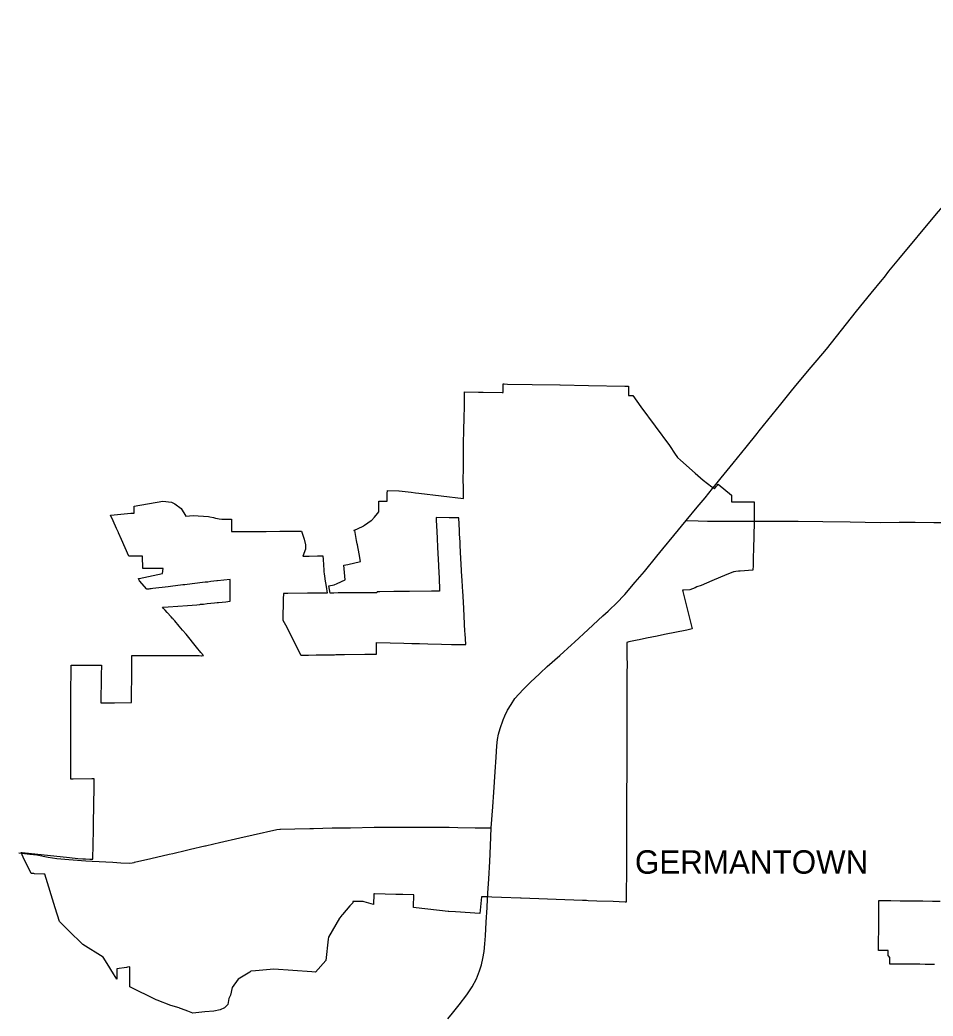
# Model space of a CAD drawing. Extents: x 0 to 34, y 0 to 22.
# Drawn here: x 4.3764 to 4.6894, y 14.3323 to 14.6736 of the extents above; entities that cross this region are included whole.
import ezdxf

# ---------------------------------------------------------------- set-up
doc = ezdxf.new("R2010")
doc.units = 0
for name, color, linetype in [('GM_X_Corporation', 7, 'Continuous'), ('GM_X_Corporation_Text', 7, 'Continuous'), ('GM_X_State_Route', 7, 'Continuous')]:
    doc.layers.add(name, color=color, linetype=linetype)

msp = doc.modelspace()

# ---------------------------------------------------------------- linework, layer by layer
at = {"layer": 'GM_X_Corporation'}
msp.add_lwpolyline([(4.41464, 14.4397), (4.41468, 14.44341), (4.41469, 14.44458), (4.41471, 14.44643), (4.41472, 14.44729), (4.41481, 14.45559), (4.41481, 14.45583), (4.4151, 14.45583), (4.41698, 14.45583), (4.42499, 14.4558), (4.43542, 14.45577), (4.43779, 14.45577), (4.43869, 14.45576), (4.4387, 14.45576), (4.43929, 14.45578), (4.43844, 14.45684), (4.43694, 14.4587), (4.43338, 14.46313), (4.43215, 14.46456), (4.43104, 14.46586), (4.42945, 14.46772), (4.42897, 14.46827), (4.4289, 14.46836), (4.42863, 14.46865), (4.42825, 14.46908), (4.42691, 14.47057), (4.42616, 14.4714), (4.42555, 14.47208), (4.42532, 14.47235), (4.42554, 14.47236), (4.42717, 14.47249), (4.43384, 14.47299), (4.43704, 14.47323), (4.43804, 14.47331), (4.43804, 14.47333), (4.43831, 14.47336), (4.43932, 14.47346), (4.4406, 14.47359), (4.44188, 14.47372), (4.44315, 14.47385), (4.444, 14.47394), (4.44443, 14.47398), (4.44571, 14.47411), (4.44699, 14.47424), (4.44771, 14.47431), (4.44843, 14.47439), (4.44844, 14.47439), (4.44844, 14.4746), (4.44845, 14.47555), (4.44845, 14.47629), (4.44845, 14.4764), (4.44846, 14.47799), (4.44847, 14.47951), (4.44847, 14.47969), (4.44848, 14.48139), (4.44848, 14.4819), (4.44409, 14.48138), (4.44394, 14.48137), (4.44189, 14.48113), (4.44081, 14.481), (4.44024, 14.48093), (4.43994, 14.4809), (4.43543, 14.48037), (4.43291, 14.48007), (4.43268, 14.48005), (4.43221, 14.47999), (4.42804, 14.4795), (4.42716, 14.4794), (4.42196, 14.47878), (4.42139, 14.47871), (4.42091, 14.47865), (4.42059, 14.47861), (4.41994, 14.47854), (4.41744, 14.48144), (4.4171, 14.4822), (4.41726, 14.48223), (4.42523, 14.4839), (4.4255, 14.48559), (4.41853, 14.48559), (4.41843, 14.48988), (4.41534, 14.48987), (4.41372, 14.48986), (4.41122, 14.49553), (4.41021, 14.49781), (4.41014, 14.49799), (4.41019, 14.49799), (4.40955, 14.49937), (4.40836, 14.50193), (4.40744, 14.50391), (4.40873, 14.50402), (4.41441, 14.50455), (4.41552, 14.50465), (4.41553, 14.50619), (4.41554, 14.50702), (4.42541, 14.50866), (4.42835, 14.50833), (4.42955, 14.5078), (4.43165, 14.50617), (4.43332, 14.50362), (4.43575, 14.50382), (4.44105, 14.5034), (4.44148, 14.50337), (4.44279, 14.50306), (4.44344, 14.50291), (4.44414, 14.50279), (4.44474, 14.5027), (4.44556, 14.50256), (4.44743, 14.50252), (4.44888, 14.50257), (4.44888, 14.50247), (4.44888, 14.50147), (4.44887, 14.49828), (4.45096, 14.4983), (4.45252, 14.49831), (4.45646, 14.49834), (4.45752, 14.49835), (4.4602, 14.49837), (4.46082, 14.49837), (4.46553, 14.49841), (4.46615, 14.49842), (4.46631, 14.49842), (4.46662, 14.49842), (4.46718, 14.49843), (4.46778, 14.49843), (4.46815, 14.49843), (4.46829, 14.49843), (4.47072, 14.49845), (4.47111, 14.49846), (4.47128, 14.49846), (4.47167, 14.49846), (4.472, 14.49846), (4.47267, 14.49847), (4.47288, 14.49847), (4.47289, 14.49845), (4.47335, 14.49709), (4.47379, 14.49573), (4.47431, 14.49376), (4.47426, 14.49222), (4.47339, 14.48985), (4.47552, 14.48989), (4.47838, 14.48995), (4.47943, 14.48997), (4.4802, 14.48998), (4.48029, 14.48874), (4.48056, 14.48505), (4.4806, 14.48455), (4.48069, 14.48377), (4.48079, 14.483), (4.4809, 14.48223), (4.48095, 14.48194), (4.48135, 14.47945), (4.48171, 14.47724), (4.48171, 14.47722), (4.48128, 14.47722), (4.48034, 14.47721), (4.48005, 14.47721), (4.47495, 14.47717), (4.46823, 14.47712), (4.46819, 14.47712), (4.46771, 14.47712), (4.46742, 14.47712), (4.46672, 14.47711), (4.46669, 14.47711), (4.46664, 14.47518), (4.46662, 14.47407), (4.46661, 14.47375), (4.46658, 14.47269), (4.46653, 14.47028), (4.46651, 14.46941), (4.4665, 14.46889), (4.46648, 14.46803), (4.46654, 14.46791), (4.46738, 14.46629), (4.47255, 14.45618), (4.47266, 14.45595), (4.4729, 14.45595), (4.47385, 14.45597), (4.47394, 14.45597), (4.47407, 14.45597), (4.47529, 14.45599), (4.47791, 14.45602), (4.47845, 14.45603), (4.47891, 14.45604), (4.48, 14.45605), (4.48068, 14.45606), (4.48418, 14.45611), (4.48467, 14.45612), (4.48514, 14.45613), (4.48678, 14.45615), (4.48762, 14.45616), (4.49468, 14.45626), (4.49784, 14.45631), (4.49861, 14.45632), (4.49862, 14.45747), (4.49864, 14.4595), (4.49864, 14.45956), (4.49864, 14.46032), (4.50803, 14.46006), (4.51068, 14.45999), (4.51333, 14.45992), (4.51626, 14.45984), (4.52091, 14.45971), (4.52434, 14.45965), (4.52816, 14.45957), (4.52897, 14.45956), (4.5292, 14.45956), (4.52896, 14.46338), (4.52892, 14.46405), (4.52852, 14.47193), (4.52828, 14.47619), (4.52819, 14.47787), (4.52811, 14.47921), (4.52797, 14.48172), (4.52791, 14.4828), (4.52768, 14.48709), (4.52757, 14.4891), (4.52732, 14.49352), (4.52725, 14.49472), (4.5271, 14.4974), (4.52703, 14.49865), (4.52679, 14.50297), (4.52353, 14.50303), (4.51907, 14.50311), (4.51911, 14.50222), (4.5193, 14.4983), (4.51941, 14.49593), (4.51955, 14.493), (4.51985, 14.48667), (4.51998, 14.484), (4.52005, 14.48258), (4.52026, 14.47807), (4.52027, 14.47787), (4.51749, 14.47785), (4.50994, 14.47778), (4.50927, 14.47777), (4.50461, 14.47773), (4.49981, 14.47769), (4.4988, 14.47768), (4.49879, 14.47735), (4.49747, 14.47734), (4.49342, 14.47731), (4.4915, 14.4773), (4.49079, 14.47729), (4.48985, 14.47729), (4.48851, 14.47728), (4.48778, 14.47727), (4.48622, 14.47726), (4.48543, 14.47725), (4.48398, 14.47724), (4.48269, 14.47723), (4.48228, 14.47974), (4.48406, 14.47999), (4.48512, 14.48048), (4.48785, 14.48177), (4.48738, 14.48675), (4.48876, 14.48704), (4.49317, 14.48799), (4.49268, 14.49061), (4.4921, 14.49371), (4.49202, 14.49412), (4.49182, 14.4952), (4.49123, 14.49861), (4.49084, 14.49861), (4.49087, 14.49863), (4.49402, 14.50015), (4.49422, 14.50029), (4.49451, 14.50049), (4.49674, 14.50204), (4.49687, 14.50213), (4.4979, 14.50319), (4.49897, 14.50452), (4.49898, 14.50454), (4.4994, 14.50507), (4.4994, 14.50559), (4.4994, 14.50776), (4.4994, 14.50789), (4.4994, 14.50868), (4.50146, 14.50869), (4.50227, 14.5087), (4.50232, 14.51133), (4.50234, 14.51237), (4.50623, 14.51227), (4.50634, 14.51225), (4.5084, 14.512), (4.51052, 14.51174), (4.51196, 14.51156), (4.51313, 14.51142), (4.52844, 14.50968), (4.52843, 14.5115), (4.52842, 14.51201), (4.52838, 14.51738), (4.5284, 14.51849), (4.5284, 14.51887), (4.52844, 14.52251), (4.52845, 14.52358), (4.52847, 14.52555), (4.52848, 14.52659), (4.52848, 14.52679), (4.5285, 14.52816), (4.5285, 14.52825), (4.52859, 14.53324), (4.52866, 14.53708), (4.52867, 14.53753), (4.52873, 14.54088), (4.52875, 14.54182), (4.52883, 14.54612), (4.5336, 14.54606), (4.53516, 14.54605), (4.54173, 14.54598), (4.54205, 14.54597), (4.54205, 14.54617), (4.54209, 14.54887), (4.54242, 14.54887), (4.54352, 14.54885), (4.55196, 14.5487), (4.5615, 14.54853), (4.56163, 14.54853), (4.57124, 14.54837), (4.58376, 14.54815), (4.58505, 14.54813), (4.58501, 14.54492), (4.58644, 14.54488), (4.58925, 14.54106), (4.599, 14.52776), (4.59924, 14.52741), (4.60078, 14.52517), (4.60185, 14.52363), (4.60282, 14.52278), (4.60789, 14.51831), (4.61056, 14.51596), (4.61361, 14.51365), (4.61399, 14.51336), (4.61401, 14.51334), (4.61448, 14.51294), (4.61449, 14.51294), (4.61519, 14.51382), (4.6155, 14.51419), (4.61573, 14.51449), (4.6203, 14.5108), (4.6203, 14.50851), (4.62289, 14.5085), (4.62549, 14.50848), (4.62809, 14.50847), (4.62808, 14.50422), (4.62807, 14.50262), (4.62806, 14.50197), (4.62804, 14.50149), (4.62782, 14.49228), (4.62775, 14.48949), (4.62768, 14.48665), (4.62764, 14.48512), (4.62327, 14.48472), (4.6227, 14.48467), (4.6218, 14.48459), (4.62123, 14.48454), (4.62101, 14.48452), (4.62073, 14.4844), (4.61875, 14.48358), (4.6136, 14.48143), (4.60985, 14.47987), (4.60847, 14.4793), (4.60788, 14.47905), (4.60602, 14.47828), (4.60401, 14.4782), (4.60366, 14.47818), (4.60353, 14.47818), (4.60684, 14.46494), (4.60502, 14.46456), (4.59731, 14.46298), (4.59482, 14.46246), (4.59122, 14.46172), (4.58866, 14.4612), (4.58798, 14.46106), (4.58509, 14.46046), (4.58477, 14.46039), (4.58438, 14.46031), (4.58438, 14.45944), (4.58439, 14.45905), (4.58439, 14.459), (4.58441, 14.45625), (4.58441, 14.45479), (4.58449, 14.45327), (4.58447, 14.44937), (4.58447, 14.44736), (4.58443, 14.43472), (4.58442, 14.43171), (4.58441, 14.42931), (4.58438, 14.41858), (4.58439, 14.41632), (4.58439, 14.41557), (4.58438, 14.4135), (4.58438, 14.41269), (4.58437, 14.41168), (4.58437, 14.41028), (4.58436, 14.40904), (4.58435, 14.40791), (4.58435, 14.40651), (4.58433, 14.40285), (4.58431, 14.39712), (4.58431, 14.39648), (4.5843, 14.39459), (4.5843, 14.39417), (4.58429, 14.39203), (4.58429, 14.39149), (4.58429, 14.39028), (4.58429, 14.38921), (4.58429, 14.38787), (4.58428, 14.38602), (4.58429, 14.38225), (4.58425, 14.37383), (4.58423, 14.37133), (4.58387, 14.37134), (4.5798, 14.37149), (4.57409, 14.3717), (4.5712, 14.37181), (4.57063, 14.37183), (4.56945, 14.37188), (4.56925, 14.37188), (4.5482, 14.37266), (4.54802, 14.37267), (4.54144, 14.37292), (4.53816, 14.37304), (4.53675, 14.37309), (4.53486, 14.37316), (4.5346, 14.37317), (4.53408, 14.36744), (4.53403, 14.36744), (4.52575, 14.36796), (4.52342, 14.36811), (4.52324, 14.36812), (4.51219, 14.36934), (4.51135, 14.36943), (4.51136, 14.3697), (4.51145, 14.37378), (4.50762, 14.37388), (4.50675, 14.37391), (4.50618, 14.37392), (4.50572, 14.37393), (4.50562, 14.37394), (4.50529, 14.37394), (4.49798, 14.37414), (4.49774, 14.37414), (4.4977, 14.37314), (4.49769, 14.37305), (4.49762, 14.37148), (4.49758, 14.37053), (4.49677, 14.37076), (4.49439, 14.37142), (4.49404, 14.37151), (4.49378, 14.37153), (4.49317, 14.37154), (4.49162, 14.37155), (4.4912, 14.37156), (4.49113, 14.37156), (4.49087, 14.37156), (4.49049, 14.37157), (4.49049, 14.37139), (4.49055, 14.37111), (4.4905, 14.37105), (4.48971, 14.37026), (4.48949, 14.37001), (4.487, 14.36708), (4.48678, 14.36682), (4.48648, 14.36647), (4.48598, 14.3658), (4.48218, 14.35927), (4.48211, 14.35866), (4.48128, 14.35137), (4.47776, 14.3473), (4.47646, 14.34739), (4.46341, 14.34831), (4.45713, 14.34775), (4.45565, 14.34762), (4.45556, 14.34761), (4.4552, 14.34737), (4.45126, 14.34488), (4.44917, 14.34208), (4.44863, 14.33945), (4.44805, 14.33834), (4.44766, 14.33624), (4.44647, 14.33513), (4.44509, 14.33441), (4.44291, 14.3339), (4.43976, 14.33368), (4.43567, 14.33323), (4.43395, 14.33393), (4.43173, 14.3348), (4.43114, 14.33503), (4.43102, 14.33507), (4.42812, 14.33588), (4.42342, 14.33772), (4.42308, 14.33786), (4.41412, 14.3423), (4.41413, 14.34829), (4.41413, 14.34909), (4.41328, 14.34898), (4.41297, 14.34894), (4.40966, 14.3485), (4.40966, 14.34531), (4.40966, 14.34488), (4.40846, 14.34679), (4.40626, 14.35027), (4.4049, 14.35244), (4.39799, 14.3568), (4.39308, 14.36165), (4.39184, 14.36287), (4.39, 14.36468), (4.38852, 14.36936), (4.38489, 14.38089), (4.38463, 14.3809), (4.38144, 14.38107), (4.3812, 14.38109), (4.38023, 14.38114), (4.37757, 14.38675), (4.37681, 14.38835), (4.37722, 14.38831), (4.39336, 14.38656), (4.39627, 14.38632), (4.39794, 14.38619), (4.39891, 14.38614), (4.40038, 14.38605), (4.40073, 14.38603), (4.40144, 14.38599), (4.40159, 14.39611), (4.40167, 14.40085), (4.40168, 14.40186), (4.40186, 14.41347), (4.40186, 14.41352), (4.40182, 14.41352), (4.40105, 14.41352), (4.40105, 14.41352), (4.39467, 14.41348), (4.3938, 14.41348), (4.3938, 14.41397), (4.39381, 14.4163), (4.39382, 14.42031), (4.39385, 14.42877), (4.39385, 14.43059), (4.39386, 14.43208), (4.39387, 14.43583), (4.39389, 14.44182), (4.39392, 14.45246), (4.3953, 14.45247), (4.40039, 14.45251), (4.40377, 14.45253), (4.40433, 14.45254), (4.40432, 14.45229), (4.40429, 14.44937), (4.40426, 14.44725), (4.40418, 14.44084), (4.40416, 14.4396), (4.40881, 14.43965)], close=True, dxfattribs=at)
msp.add_lwpolyline([(4.68985, 14.34997), (4.68674, 14.34999), (4.68484, 14.35001), (4.683, 14.35002), (4.68253, 14.35002), (4.68229, 14.35003), (4.68161, 14.35003), (4.68097, 14.35004), (4.67879, 14.35005), (4.67563, 14.35007), (4.67454, 14.35008), (4.67454, 14.35172), (4.67455, 14.35237), (4.67408, 14.35286), (4.67399, 14.35295), (4.67405, 14.3547), (4.67353, 14.3547), (4.67068, 14.35472), (4.67068, 14.3554), (4.6707, 14.3572), (4.67075, 14.3625), (4.67076, 14.36413), (4.67077, 14.36463), (4.6708, 14.36744), (4.67083, 14.36949), (4.67084, 14.37085), (4.67085, 14.37188), (4.67221, 14.37186), (4.67497, 14.37183), (4.67815, 14.37179), (4.68226, 14.37175), (4.68353, 14.37173), (4.68475, 14.37172), (4.68586, 14.37171), (4.6892, 14.37167), (4.69179, 14.37164)], dxfattribs=at)
at = {"layer": 'GM_X_State_Route'}
for p, q in [((4.57798, 14.471), (4.57858, 14.47157)), ((4.52311, 14.33132), (4.52468, 14.33327))]:
    msp.add_line(p, q, dxfattribs=at)
for points in [[(4.67425, 14.58751), (4.67767, 14.59166), (4.69056, 14.6072), (4.6927, 14.6097), (4.69743, 14.6154), (4.70004, 14.61862), (4.70413, 14.62384), (4.70902, 14.63035), (4.71286, 14.63549), (4.71914, 14.64394), (4.74073, 14.67225), (4.74179, 14.67361)], [(4.67195, 14.5846), (4.67269, 14.58552), (4.67425, 14.58751)], [(4.62976, 14.53276), (4.63719, 14.54196), (4.64091, 14.54652), (4.64298, 14.54902), (4.64761, 14.55459), (4.64963, 14.557), (4.65283, 14.56085), (4.66319, 14.57386), (4.66819, 14.58), (4.67195, 14.5846)], [(4.6149, 14.51442), (4.61671, 14.51665), (4.62084, 14.52169), (4.62531, 14.52723), (4.62907, 14.53191), (4.62976, 14.53276)], [(4.60473, 14.50206), (4.60858, 14.50669), (4.61125, 14.5099), (4.61384, 14.5131), (4.6149, 14.51442)], [(4.58377, 14.47678), (4.58731, 14.48092), (4.59044, 14.48465), (4.59472, 14.48981), (4.5968, 14.49234), (4.60053, 14.49689), (4.60473, 14.50206)], [(4.60473, 14.50206), (4.60887, 14.50195), (4.61213, 14.5019), (4.62094, 14.50181), (4.62553, 14.50183), (4.62749, 14.50188)], [(4.62749, 14.50188), (4.62876, 14.50191), (4.63087, 14.50186), (4.63625, 14.50186), (4.63938, 14.50186), (4.64318, 14.50182), (4.65163, 14.50174), (4.66099, 14.50165), (4.67127, 14.50145)], [(4.67127, 14.50145), (4.67778, 14.50149), (4.68322, 14.50148), (4.68968, 14.50141), (4.69377, 14.50136), (4.70177, 14.5013), (4.71183, 14.50119), (4.72194, 14.50107), (4.72894, 14.50099), (4.73136, 14.50096), (4.73821, 14.50091), (4.74295, 14.50089), (4.75114, 14.50079), (4.7577, 14.50079)], [(4.57858, 14.47157), (4.58078, 14.47366), (4.58372, 14.47671), (4.58377, 14.47678)], [(4.56548, 14.45949), (4.56649, 14.4604), (4.57121, 14.46469), (4.57624, 14.46941), (4.57798, 14.471)], [(4.55475, 14.44983), (4.55714, 14.45201), (4.56144, 14.45582), (4.56548, 14.45949)], [(4.54357, 14.43708), (4.54483, 14.43907), (4.54608, 14.44106), (4.54738, 14.44262), (4.549, 14.44432), (4.55149, 14.44682), (4.55437, 14.44948), (4.55475, 14.44983)], [(4.53794, 14.39681), (4.53854, 14.404), (4.53887, 14.40898), (4.53927, 14.41598), (4.5396, 14.42103), (4.53985, 14.42484), (4.54014, 14.42708), (4.54049, 14.42888), (4.54096, 14.43077), (4.54199, 14.43379), (4.5426, 14.4352), (4.54357, 14.43708)], [(4.41571, 14.38497), (4.42132, 14.3863), (4.42755, 14.38774), (4.42876, 14.38802), (4.43353, 14.38914), (4.43394, 14.38923), (4.43487, 14.38942), (4.43979, 14.39056), (4.43998, 14.3906), (4.44284, 14.39125), (4.44484, 14.39171), (4.45179, 14.39331), (4.45631, 14.39435), (4.46447, 14.39623), (4.46554, 14.39635), (4.4657, 14.39635)], [(4.4657, 14.39635), (4.47062, 14.39645), (4.47574, 14.39655)], [(4.47574, 14.39655), (4.47701, 14.39658), (4.48348, 14.39672), (4.48967, 14.39683), (4.49782, 14.39701), (4.50276, 14.39706)], [(4.50276, 14.39706), (4.50737, 14.39705), (4.51605, 14.39703), (4.51977, 14.397), (4.52349, 14.39696), (4.52653, 14.39692), (4.53242, 14.39683), (4.53794, 14.39681)], [(4.53679, 14.37435), (4.53709, 14.37926), (4.53745, 14.38529), (4.53767, 14.39064), (4.53794, 14.39681)], [(4.37599, 14.38818), (4.37608, 14.38817), (4.37983, 14.38779), (4.38222, 14.38751), (4.38603, 14.38676), (4.38904, 14.3863), (4.39313, 14.38594), (4.39901, 14.38551), (4.40121, 14.38541), (4.4083, 14.38496), (4.41104, 14.38479), (4.4141, 14.3847), (4.41485, 14.38478), (4.41555, 14.38493), (4.41571, 14.38497)], [(4.52468, 14.33327), (4.52697, 14.33615), (4.52958, 14.33956), (4.53139, 14.34228), (4.53286, 14.34506), (4.53394, 14.34774), (4.53459, 14.34979), (4.53512, 14.35196), (4.53551, 14.3544), (4.53578, 14.35699), (4.53594, 14.35982), (4.53622, 14.36442), (4.53652, 14.36948), (4.53668, 14.37229), (4.53678, 14.37418), (4.53679, 14.37435)]]:
    msp.add_lwpolyline(points, dxfattribs=at)

# ---------------------------------------------------------------- texts
at = {"layer": 'GM_X_Corporation_Text'}
msp.add_text('GERMANTOWN', height=0.008037, rotation=0, dxfattribs=at).set_placement((4.5872, 14.38105))

doc.saveas('drawing.dxf')
